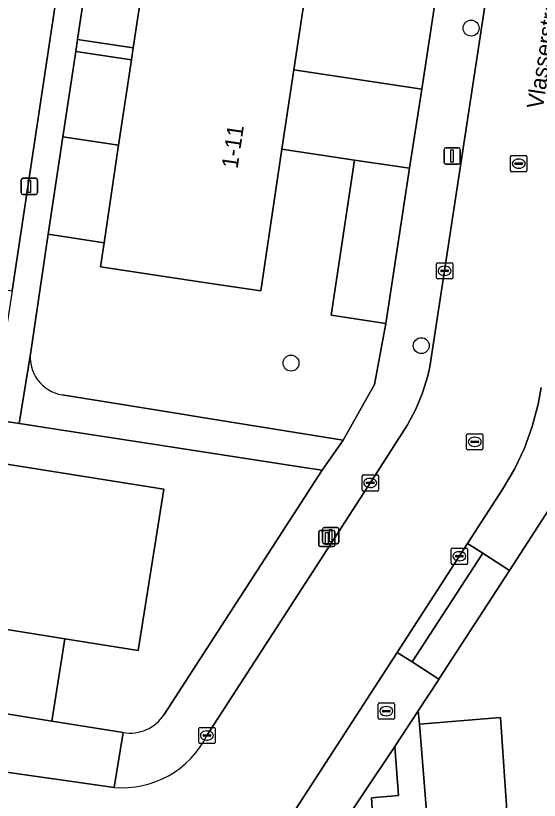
# Model space of a CAD drawing. Extents: x 161084 to 161928, y 385354 to 386522.
# Drawn here: x 161687.58 to 161719.79, y 385406.54 to 385454.78 of the extents above; entities that cross this region are included whole.
import ezdxf

# ---------------------------------------------------------------- set-up
doc = ezdxf.new("R2010")
doc.units = 0
for name, color, linetype in [('IMGEO_Boom', 7, 'Continuous'), ('IMGEO_Brandkraan', 7, 'Continuous'), ('IMGEO_Groenvoorziening', 7, 'Continuous'), ('IMGEO_Kolk', 7, 'Continuous'), ('IMGEO_Lichtmast', 7, 'Continuous'), ('IMGEO_Openbare_ruimte_label', 7, 'Continuous'), ('IMGEO_Pand', 7, 'Continuous'), ('IMGEO_Pand_nummerreeks', 7, 'Continuous'), ('IMGEO_Parkeervlak_open', 7, 'Continuous'), ('IMGEO_Rijbaan_lokaal_open', 7, 'Continuous'), ('IMGEO_Rioolput', 7, 'Continuous'), ('IMGEO_Voetpad_open', 7, 'Continuous')]:
    doc.layers.add(name, color=color, linetype=linetype)

msp = doc.modelspace()

# ---------------------------------------------------------------- linework, layer by layer
at = {"layer": 'IMGEO_Boom'}
for centre in [(161715.594, 385454.012), (161712.528, 385434.49), (161704.516, 385433.417)]:
    msp.add_circle(centre, 0.489, dxfattribs=at)
at = {"layer": 'IMGEO_Brandkraan'}
for p, q in [((161709.877, 385411.593), (161709.877, 385412.445)), ((161709.952, 385412.519), (161710.804, 385412.519)), ((161710.878, 385412.445), (161710.878, 385411.593)), ((161710.136, 385412.013), (161710.136, 385412.025)), ((161710.574, 385411.976), (161710.176, 385411.976)), ((161710.179, 385412.062), (161710.577, 385412.062)), ((161710.365, 385412.299), (161710.39, 385412.299)), ((161710.62, 385412.025), (161710.62, 385412.013)), ((161710.804, 385411.519), (161709.952, 385411.519)), ((161710.388, 385411.739), (161710.363, 385411.739))]:
    msp.add_line(p, q, dxfattribs=at)
for points in [[(161709.877, 385411.593), (161709.877, 385412.445)], [(161709.952, 385412.519), (161710.804, 385412.519)], [(161710.878, 385412.445), (161710.878, 385411.593)], [(161710.804, 385411.519), (161709.952, 385411.519)]]:
    msp.add_lwpolyline(points, dxfattribs=at)
for centre, radius, start, end in [((161709.954, 385412.443), 0.0765, 91.552, 178.448), ((161709.954, 385412.443), 0.0765, 91.552, 178.448), ((161710.802, 385412.443), 0.0765, 1.552, 88.448), ((161710.802, 385412.443), 0.0765, 1.552, 88.448), ((161710.176, 385412.022), 0.0403, 85.8775, 175.7526), ((161710.173, 385412.012), 0.0366, 178.938, 274.7102), ((161710.577, 385412.019), 0.043, 264.8664, 352.4533), ((161710.581, 385412.024), 0.0386, 1.7309, 96.639), ((161709.954, 385411.595), 0.0765, 181.552, 268.448), ((161709.954, 385411.595), 0.0765, 181.552, 268.448), ((161710.802, 385411.595), 0.0765, 271.552, 358.448), ((161710.802, 385411.595), 0.0765, 271.552, 358.448)]:
    msp.add_arc(centre, radius, start, end, dxfattribs=at)
for centre, major_axis, ratio, start_param, end_param in [((161710.364, 385412.019), (-0.387, 0.002), 0.722429, 4.712389, 7.853982), ((161710.389, 385412.019), (-0.39, 0.002), 0.717154, 1.570796, 4.712389)]:
    msp.add_ellipse(centre, major_axis=major_axis, ratio=ratio, start_param=start_param, end_param=end_param, dxfattribs=at)
at = {"layer": 'IMGEO_Groenvoorziening'}
for points in [[(161687.355, 385437.87), (161694.277, 385483.736), (161687.851, 385484.707), (161690.149, 385500), (161691.027, 385505.856), (161697.457, 385504.857), (161700.47, 385525.043), (161684.952, 385527.492), (161683.871, 385520.546), (161668.88, 385522.726), (161665.355, 385500), (161656.719, 385442.697)], [(161691.376, 385453.312), (161694.805, 385452.798), (161695.454, 385457.13), (161696.226, 385462.28), (161692.797, 385462.794)], [(161713.836, 385458.629), (161705.941, 385459.812), (161705.317, 385455.652), (161704.686, 385451.442), (161712.558, 385450.262)], [(161690.48, 385447.333), (161693.909, 385446.819), (161694.695, 385452.067), (161691.266, 385452.58)], [(161689.58, 385441.334), (161693.009, 385440.82), (161693.909, 385446.819), (161690.48, 385447.333)], [(161711.814, 385445.393), (161708.415, 385445.902), (161706.985, 385436.363), (161710.357, 385435.857)], [(161709.898, 385403.712), (161709.732, 385404.805), (161709.593, 385404.787), (161709.461, 385406.683), (161711.129, 385406.825), (161710.899, 385409.84), (161707.126, 385404.205), (161707.618, 385403.859), (161708.111, 385403.512)]]:
    msp.add_lwpolyline(points, close=True, dxfattribs=at)
for points in [[(161706.985, 385436.363), (161708.415, 385445.902), (161703.956, 385446.57), (161702.649, 385437.851), (161700.144, 385438.226), (161699.027, 385438.394), (161692.786, 385439.329), (161693.009, 385440.82), (161689.58, 385441.334), (161688.497, 385434.107)], [(161690.433, 385431.463), (161697.81, 385430.275), (161698.925, 385430.095), (161707.714, 385428.679), (161709.654, 385432.105), (161710.357, 385435.857), (161706.985, 385436.363)], [(161706.433, 385426.827), (161705.715, 385426.938), (161698.294, 385428.083), (161697.099, 385428.267), (161689.366, 385429.461), (161688.35, 385429.618), (161687.795, 385429.703), (161679.607, 385430.967), (161670.074, 385432.438), (161668.914, 385432.617), (161655.732, 385434.651), (161653.669, 385434.969), (161652.029, 385435.264)], [(161662.949, 385415.678), (161663.754, 385420.742), (161659.187, 385421.469), (161659.876, 385425.794), (161660.033, 385426.782), (161660.765, 385431.379), (161668.52, 385430.144), (161669.679, 385429.959), (161678.593, 385428.539), (161687.94, 385427.051), (161688.957, 385426.889), (161696.683, 385425.658), (161695.843, 385420.388), (161695.104, 385415.749), (161690.598, 385416.467), (161689.792, 385411.399), (161694.189, 385410.698)], [(161696.714, 385411.815), (161706.433, 385426.827)]]:
    msp.add_lwpolyline(points, dxfattribs=at)
for centre, radius, start, end in [((161690.802, 385433.764), 2.33, 171.5383, 260.8867), ((161694.593, 385413.198), 2.532, 260.8244, 326.9025)]:
    msp.add_arc(centre, radius, start, end, dxfattribs=at)
at = {"layer": 'IMGEO_Kolk'}
for p, q in [((161713.465, 385438.665), (161713.465, 385439.517)), ((161713.54, 385439.591), (161714.392, 385439.591)), ((161714.466, 385439.517), (161714.466, 385438.665)), ((161713.724, 385439.085), (161713.724, 385439.097)), ((161714.162, 385439.048), (161713.764, 385439.048)), ((161713.767, 385439.134), (161714.165, 385439.134)), ((161713.953, 385439.371), (161713.978, 385439.371)), ((161714.208, 385439.097), (161714.208, 385439.085)), ((161714.392, 385438.591), (161713.54, 385438.591)), ((161713.976, 385438.811), (161713.951, 385438.811)), ((161708.888, 385425.622), (161708.888, 385426.474)), ((161708.963, 385426.548), (161709.815, 385426.548)), ((161709.889, 385426.474), (161709.889, 385425.622)), ((161709.147, 385426.042), (161709.147, 385426.054)), ((161709.585, 385426.005), (161709.187, 385426.005)), ((161709.19, 385426.091), (161709.588, 385426.091)), ((161709.376, 385426.328), (161709.401, 385426.328)), ((161709.631, 385426.054), (161709.631, 385426.042)), ((161709.815, 385425.548), (161708.963, 385425.548)), ((161709.399, 385425.768), (161709.374, 385425.768)), ((161714.37, 385421.117), (161714.37, 385421.969)), ((161714.445, 385422.043), (161715.297, 385422.043)), ((161714.672, 385421.586), (161715.07, 385421.586)), ((161714.858, 385421.823), (161714.883, 385421.823)), ((161715.371, 385421.969), (161715.371, 385421.117)), ((161714.629, 385421.537), (161714.629, 385421.549)), ((161715.067, 385421.5), (161714.669, 385421.5)), ((161714.881, 385421.263), (161714.856, 385421.263)), ((161715.113, 385421.549), (161715.113, 385421.537)), ((161715.297, 385421.043), (161714.445, 385421.043)), ((161698.916, 385411.02), (161699.768, 385411.02)), ((161698.841, 385410.094), (161698.841, 385410.946)), ((161699.1, 385410.514), (161699.1, 385410.526)), ((161699.538, 385410.477), (161699.14, 385410.477)), ((161699.143, 385410.563), (161699.541, 385410.563)), ((161699.329, 385410.8), (161699.354, 385410.8)), ((161699.584, 385410.526), (161699.584, 385410.514)), ((161699.842, 385410.946), (161699.842, 385410.094)), ((161699.768, 385410.02), (161698.916, 385410.02)), ((161699.352, 385410.24), (161699.327, 385410.24))]:
    msp.add_line(p, q, dxfattribs=at)
for points in [[(161713.465, 385438.665), (161713.465, 385439.517)], [(161713.54, 385439.591), (161714.392, 385439.591)], [(161714.466, 385439.517), (161714.466, 385438.665)], [(161714.392, 385438.591), (161713.54, 385438.591)], [(161708.888, 385425.622), (161708.888, 385426.474)], [(161708.963, 385426.548), (161709.815, 385426.548)], [(161709.889, 385426.474), (161709.889, 385425.622)], [(161709.815, 385425.548), (161708.963, 385425.548)], [(161714.37, 385421.117), (161714.37, 385421.969)], [(161714.445, 385422.043), (161715.297, 385422.043)], [(161715.371, 385421.969), (161715.371, 385421.117)], [(161715.297, 385421.043), (161714.445, 385421.043)], [(161698.916, 385411.02), (161699.768, 385411.02)], [(161698.841, 385410.094), (161698.841, 385410.946)], [(161699.842, 385410.946), (161699.842, 385410.094)], [(161699.768, 385410.02), (161698.916, 385410.02)]]:
    msp.add_lwpolyline(points, dxfattribs=at)
for centre, radius, start, end in [((161713.542, 385439.515), 0.0765, 91.552, 178.448), ((161713.542, 385439.515), 0.0765, 91.552, 178.448), ((161714.39, 385439.515), 0.0765, 1.552, 88.448), ((161714.39, 385439.515), 0.0765, 1.552, 88.448), ((161713.764, 385439.094), 0.0403, 85.8775, 175.7526), ((161713.761, 385439.084), 0.0366, 178.938, 274.7102), ((161714.165, 385439.091), 0.043, 264.8664, 352.4533), ((161714.169, 385439.096), 0.0386, 1.7309, 96.639), ((161713.542, 385438.667), 0.0765, 181.552, 268.448), ((161713.542, 385438.667), 0.0765, 181.552, 268.448), ((161714.39, 385438.667), 0.0765, 271.552, 358.448), ((161714.39, 385438.667), 0.0765, 271.552, 358.448), ((161708.965, 385426.472), 0.0765, 91.552, 178.448), ((161708.965, 385426.472), 0.0765, 91.552, 178.448), ((161709.813, 385426.472), 0.0765, 1.552, 88.448), ((161709.813, 385426.472), 0.0765, 1.552, 88.448), ((161709.187, 385426.051), 0.0403, 85.8775, 175.7526), ((161709.184, 385426.041), 0.0366, 178.938, 274.7102), ((161709.588, 385426.048), 0.043, 264.8664, 352.4533), ((161709.592, 385426.053), 0.0386, 1.7309, 96.639), ((161708.965, 385425.624), 0.0765, 181.552, 268.448), ((161708.965, 385425.624), 0.0765, 181.552, 268.448), ((161709.813, 385425.624), 0.0765, 271.552, 358.448), ((161709.813, 385425.624), 0.0765, 271.552, 358.448), ((161714.447, 385421.967), 0.0765, 91.552, 178.448), ((161714.447, 385421.967), 0.0765, 91.552, 178.448), ((161714.669, 385421.546), 0.0403, 85.8775, 175.7526), ((161715.074, 385421.548), 0.0386, 1.7309, 96.639), ((161715.295, 385421.967), 0.0765, 1.552, 88.448), ((161715.295, 385421.967), 0.0765, 1.552, 88.448), ((161714.447, 385421.119), 0.0765, 181.552, 268.448), ((161714.447, 385421.119), 0.0765, 181.552, 268.448), ((161714.666, 385421.536), 0.0366, 178.938, 274.7102), ((161715.07, 385421.543), 0.043, 264.8664, 352.4533), ((161715.295, 385421.119), 0.0765, 271.552, 358.448), ((161715.295, 385421.119), 0.0765, 271.552, 358.448), ((161698.918, 385410.944), 0.0765, 91.552, 178.448), ((161698.918, 385410.944), 0.0765, 91.552, 178.448), ((161699.766, 385410.944), 0.0765, 1.552, 88.448), ((161699.766, 385410.944), 0.0765, 1.552, 88.448), ((161699.14, 385410.523), 0.0403, 85.8775, 175.7526), ((161699.137, 385410.513), 0.0366, 178.938, 274.7102), ((161699.541, 385410.52), 0.043, 264.8664, 352.4533), ((161699.545, 385410.525), 0.0386, 1.7309, 96.639), ((161698.918, 385410.096), 0.0765, 181.552, 268.448), ((161698.918, 385410.096), 0.0765, 181.552, 268.448), ((161699.766, 385410.096), 0.0765, 271.552, 358.448), ((161699.766, 385410.096), 0.0765, 271.552, 358.448)]:
    msp.add_arc(centre, radius, start, end, dxfattribs=at)
for centre, major_axis, ratio, start_param, end_param in [((161713.952, 385439.091), (-0.387, 0.002), 0.722429, 4.712389, 7.853982), ((161713.977, 385439.091), (-0.39, 0.002), 0.717154, 1.570796, 4.712389), ((161709.375, 385426.048), (-0.387, 0.002), 0.722429, 4.712389, 7.853982), ((161709.4, 385426.048), (-0.39, 0.002), 0.717154, 1.570796, 4.712389), ((161714.857, 385421.543), (-0.387, 0.002), 0.722429, 4.712389, 7.853982), ((161714.882, 385421.543), (-0.39, 0.002), 0.717154, 1.570796, 4.712389), ((161699.328, 385410.52), (-0.387, 0.002), 0.722429, 4.712389, 7.853982), ((161699.353, 385410.52), (-0.39, 0.002), 0.717154, 1.570796, 4.712389)]:
    msp.add_ellipse(centre, major_axis=major_axis, ratio=ratio, start_param=start_param, end_param=end_param, dxfattribs=at)
at = {"layer": 'IMGEO_Lichtmast'}
for p, q in [((161714.03, 385446.655), (161714.82, 385446.655)), ((161714.82, 385446.655), (161714.03, 385446.655)), ((161713.93, 385445.755), (161713.93, 385446.555)), ((161713.93, 385446.555), (161713.93, 385445.755)), ((161714.92, 385446.555), (161714.92, 385445.755)), ((161714.92, 385445.755), (161714.92, 385446.555)), ((161714.82, 385445.655), (161714.03, 385445.655)), ((161714.03, 385445.655), (161714.82, 385445.655)), ((161688.02, 385444.783), (161688.81, 385444.783)), ((161688.81, 385444.783), (161688.02, 385444.783)), ((161687.92, 385443.883), (161687.92, 385444.683)), ((161687.92, 385444.683), (161687.92, 385443.883)), ((161688.91, 385444.683), (161688.91, 385443.883)), ((161688.91, 385443.883), (161688.91, 385444.683)), ((161688.81, 385443.783), (161688.02, 385443.783)), ((161688.02, 385443.783), (161688.81, 385443.783)), ((161706.224, 385422.233), (161706.224, 385423.033)), ((161706.224, 385423.033), (161706.224, 385422.233)), ((161706.324, 385423.133), (161707.114, 385423.133)), ((161707.114, 385423.133), (161706.324, 385423.133)), ((161706.46, 385422.409), (161706.46, 385423.209)), ((161706.46, 385423.209), (161706.46, 385422.409)), ((161706.56, 385423.309), (161707.35, 385423.309)), ((161707.35, 385423.309), (161706.56, 385423.309)), ((161707.214, 385423.033), (161707.214, 385422.233)), ((161707.214, 385422.233), (161707.214, 385423.033)), ((161707.45, 385423.209), (161707.45, 385422.409)), ((161707.45, 385422.409), (161707.45, 385423.209)), ((161707.114, 385422.133), (161706.324, 385422.133)), ((161706.324, 385422.133), (161707.114, 385422.133)), ((161707.35, 385422.309), (161706.56, 385422.309)), ((161706.56, 385422.309), (161707.35, 385422.309))]:
    msp.add_line(p, q, dxfattribs=at)
for points in [[(161714.35, 385446.53), (161714.5, 385446.53), (161714.5, 385445.78), (161714.35, 385445.78), (161714.35, 385446.53)], [(161688.34, 385444.658), (161688.49, 385444.658), (161688.49, 385443.908), (161688.34, 385443.908), (161688.34, 385444.658)], [(161706.88, 385423.184), (161707.03, 385423.184), (161707.03, 385422.434), (161706.88, 385422.434), (161706.88, 385423.184)], [(161706.644, 385423.008), (161706.794, 385423.008), (161706.794, 385422.258), (161706.644, 385422.258), (161706.644, 385423.008)]]:
    msp.add_lwpolyline(points, dxfattribs=at)
for centre, start, end in [((161714.03, 385446.555), 90, 180), ((161714.03, 385446.555), 90, 180), ((161714.82, 385446.555), 0, 90), ((161714.82, 385446.555), 360, 90), ((161714.03, 385445.755), 180, 270), ((161714.03, 385445.755), 180, 270), ((161714.82, 385445.755), 270, 0), ((161714.82, 385445.755), 270, 0), ((161688.02, 385444.683), 90, 180), ((161688.02, 385444.683), 90, 180), ((161688.81, 385444.683), 0, 90), ((161688.81, 385444.683), 360, 90), ((161688.02, 385443.883), 180, 270), ((161688.02, 385443.883), 180, 270), ((161688.81, 385443.883), 270, 0), ((161688.81, 385443.883), 270, 0), ((161706.324, 385423.033), 90, 180), ((161706.324, 385423.033), 90, 180), ((161706.56, 385423.209), 90, 180), ((161706.56, 385423.209), 90, 180), ((161707.114, 385423.033), 0, 90), ((161707.114, 385423.033), 360, 90), ((161707.35, 385423.209), 0, 90), ((161707.35, 385423.209), 360, 90), ((161706.324, 385422.233), 180, 270), ((161706.324, 385422.233), 180, 270), ((161706.56, 385422.409), 180, 270), ((161706.56, 385422.409), 180, 270), ((161707.114, 385422.233), 270, 0), ((161707.114, 385422.233), 270, 0), ((161707.35, 385422.409), 270, 0), ((161707.35, 385422.409), 270, 0)]:
    msp.add_arc(centre, 0.1, start, end, dxfattribs=at)
at = {"layer": 'IMGEO_Pand'}
for points in [[(161705.317, 385455.652), (161695.454, 385457.13), (161694.805, 385452.798), (161694.695, 385452.067), (161693.909, 385446.819), (161693.009, 385440.82), (161692.786, 385439.329), (161699.027, 385438.394), (161700.144, 385438.226), (161702.649, 385437.851), (161703.956, 385446.57), (161704.686, 385451.442)], [(161683.3, 385417.629), (161687.035, 385417.034), (161690.598, 385416.467), (161695.104, 385415.749), (161695.843, 385420.388), (161696.683, 385425.658), (161688.957, 385426.889), (161687.94, 385427.051), (161678.593, 385428.539), (161677.015, 385418.63)]]:
    msp.add_lwpolyline(points, close=True, dxfattribs=at)
at = {"layer": 'IMGEO_Parkeervlak_open'}
msp.add_lwpolyline([(161717.4, 385411.626), (161712.409, 385411.224), (161713.131, 385402.28), (161718.019, 385402.612)], close=True, dxfattribs=at)
at = {"layer": 'IMGEO_Rijbaan_lokaal_open'}
for points in [[(161723.237, 385500), (161713.061, 385433.189), (161712.927, 385432.624), (161712.605, 385431.585), (161712.19, 385430.579), (161711.688, 385429.614), (161709.663, 385426.482), (161699.341, 385410.516)], [(161704.565, 385405.627), (161711.043, 385415.632), (161715.381, 385422.332), (161717.547, 385425.678), (161718.264, 385426.902), (161718.869, 385428.185), (161719.356, 385429.517), (161719.723, 385430.887), (161719.914, 385431.913)], [(161720.617, 385424.785), (161717.947, 385420.67), (161713.609, 385413.983), (161713.603, 385413.974), (161712.344, 385412.033), (161712.409, 385411.224), (161717.4, 385411.626), (161718.019, 385402.612), (161724.677, 385403.063)], [(161693.625, 385407.334), (161671.022, 385410.55), (161662.632, 385411.873), (161658.399, 385412.541), (161654.604, 385413.143)]]:
    msp.add_lwpolyline(points, dxfattribs=at)
msp.add_arc((161694.128, 385413.155), 5.843, 265.0607, 333.1472, dxfattribs=at)
at = {"layer": 'IMGEO_Rioolput'}
for p, q in [((161718.098, 385446.18), (161718.95, 385446.18)), ((161718.023, 385445.254), (161718.023, 385446.106)), ((161718.282, 385445.674), (161718.282, 385445.686)), ((161718.325, 385445.723), (161718.723, 385445.723)), ((161718.511, 385445.96), (161718.536, 385445.96)), ((161718.766, 385445.686), (161718.766, 385445.674)), ((161719.024, 385446.106), (161719.024, 385445.254)), ((161718.72, 385445.637), (161718.322, 385445.637)), ((161718.534, 385445.4), (161718.509, 385445.4)), ((161718.95, 385445.18), (161718.098, 385445.18)), ((161715.319, 385428.15), (161715.319, 385429.002)), ((161715.394, 385429.076), (161716.246, 385429.076)), ((161715.807, 385428.856), (161715.832, 385428.856)), ((161716.32, 385429.002), (161716.32, 385428.15)), ((161715.578, 385428.57), (161715.578, 385428.582)), ((161716.016, 385428.533), (161715.618, 385428.533)), ((161715.621, 385428.619), (161716.019, 385428.619)), ((161716.062, 385428.582), (161716.062, 385428.57)), ((161716.246, 385428.076), (161715.394, 385428.076)), ((161715.83, 385428.296), (161715.805, 385428.296))]:
    msp.add_line(p, q, dxfattribs=at)
for points in [[(161718.098, 385446.18), (161718.95, 385446.18)], [(161718.023, 385445.254), (161718.023, 385446.106)], [(161719.024, 385446.106), (161719.024, 385445.254)], [(161718.95, 385445.18), (161718.098, 385445.18)], [(161715.319, 385428.15), (161715.319, 385429.002)], [(161715.394, 385429.076), (161716.246, 385429.076)], [(161716.32, 385429.002), (161716.32, 385428.15)], [(161716.246, 385428.076), (161715.394, 385428.076)]]:
    msp.add_lwpolyline(points, dxfattribs=at)
for centre, radius, start, end in [((161718.1, 385446.104), 0.0765, 91.552, 178.448), ((161718.1, 385446.104), 0.0765, 91.552, 178.448), ((161718.948, 385446.104), 0.0765, 1.552, 88.448), ((161718.948, 385446.104), 0.0765, 1.552, 88.448), ((161718.322, 385445.683), 0.0403, 85.8775, 175.7526), ((161718.727, 385445.685), 0.0386, 1.7309, 96.639), ((161718.1, 385445.256), 0.0765, 181.552, 268.448), ((161718.1, 385445.256), 0.0765, 181.552, 268.448), ((161718.319, 385445.673), 0.0366, 178.938, 274.7102), ((161718.723, 385445.68), 0.043, 264.8664, 352.4533), ((161718.948, 385445.256), 0.0765, 271.552, 358.448), ((161718.948, 385445.256), 0.0765, 271.552, 358.448), ((161715.396, 385429), 0.0765, 91.552, 178.448), ((161715.396, 385429), 0.0765, 91.552, 178.448), ((161716.244, 385429), 0.0765, 1.552, 88.448), ((161716.244, 385429), 0.0765, 1.552, 88.448), ((161715.618, 385428.579), 0.0403, 85.8775, 175.7526), ((161715.615, 385428.569), 0.0366, 178.938, 274.7102), ((161716.019, 385428.576), 0.043, 264.8664, 352.4533), ((161716.023, 385428.581), 0.0386, 1.7309, 96.639), ((161715.396, 385428.152), 0.0765, 181.552, 268.448), ((161715.396, 385428.152), 0.0765, 181.552, 268.448), ((161716.244, 385428.152), 0.0765, 271.552, 358.448), ((161716.244, 385428.152), 0.0765, 271.552, 358.448)]:
    msp.add_arc(centre, radius, start, end, dxfattribs=at)
for centre, major_axis, ratio, start_param, end_param in [((161718.51, 385445.68), (-0.387, 0.002), 0.722429, 4.712389, 7.853982), ((161718.535, 385445.68), (-0.39, 0.002), 0.717154, 1.570796, 4.712389), ((161715.806, 385428.576), (-0.387, 0.002), 0.722429, 4.712389, 7.853982), ((161715.831, 385428.576), (-0.39, 0.002), 0.717154, 1.570796, 4.712389)]:
    msp.add_ellipse(centre, major_axis=major_axis, ratio=ratio, start_param=start_param, end_param=end_param, dxfattribs=at)
at = {"layer": 'IMGEO_Voetpad_open'}
for points in [[(161699.341, 385410.516), (161709.663, 385426.482), (161711.688, 385429.614), (161712.19, 385430.579), (161712.605, 385431.585), (161712.927, 385432.624), (161713.061, 385433.189), (161723.237, 385500), (161727.669, 385529.274), (161727.823, 385530.11), (161731.045, 385551.389), (161732.828, 385563.446)], [(161656.268, 385438.891), (161655.732, 385434.651), (161668.914, 385432.617), (161670.074, 385432.438), (161679.607, 385430.967), (161687.795, 385429.703), (161688.497, 385434.107), (161689.58, 385441.334), (161690.48, 385447.333), (161691.266, 385452.58), (161691.376, 385453.312), (161692.797, 385462.794), (161692.94, 385463.744), (161696.643, 385488.449), (161696.796, 385489.473), (161698.167, 385498.626), (161698.304, 385499.531), (161698.375, 385500), (161701.928, 385523.472), (161702.137, 385524.559), (161707.374, 385558.705)], [(161707.374, 385558.705), (161705.534, 385558.969), (161704.956, 385555.095), (161702.756, 385540.358), (161702.189, 385536.561), (161700.47, 385525.043), (161697.457, 385504.857), (161696.732, 385500), (161694.277, 385483.736), (161687.355, 385437.87), (161686.853, 385434.542)], [(161720.039, 385499.232), (161719.339, 385494.65), (161718.003, 385485.908), (161717.296, 385481.276), (161714.579, 385463.494), (161713.836, 385458.629), (161712.558, 385450.262), (161711.814, 385445.393), (161710.357, 385435.857), (161709.654, 385432.105), (161707.714, 385428.679), (161706.433, 385426.827), (161696.714, 385411.815)], [(161688.497, 385434.107), (161687.795, 385429.703), (161688.35, 385429.618), (161689.366, 385429.461), (161697.099, 385428.267), (161698.294, 385428.083), (161705.715, 385426.938), (161706.433, 385426.827), (161707.714, 385428.679), (161698.925, 385430.095)], [(161719.914, 385431.913), (161719.723, 385430.887), (161719.356, 385429.517), (161718.869, 385428.185), (161718.264, 385426.902), (161717.547, 385425.678), (161715.381, 385422.332), (161716.311, 385421.731), (161717.947, 385420.67), (161720.617, 385424.785)], [(161698.925, 385430.095), (161697.81, 385430.275), (161690.433, 385431.463)], [(161662.521, 385415.355), (161655.13, 385416.518), (161654.604, 385413.143), (161658.399, 385412.541), (161662.632, 385411.873), (161671.022, 385410.55), (161693.625, 385407.334), (161694.189, 385410.698), (161689.792, 385411.399), (161686.229, 385411.967), (161682.494, 385412.562)], [(161707.126, 385404.205), (161710.899, 385409.84), (161712.344, 385412.033), (161713.603, 385413.974), (161713.609, 385413.983), (161711.973, 385415.044), (161711.043, 385415.632), (161704.565, 385405.627)], [(161694.189, 385410.698), (161693.625, 385407.334)]]:
    msp.add_lwpolyline(points, dxfattribs=at)
for points in [[(161691.266, 385452.58), (161694.695, 385452.067), (161694.805, 385452.798), (161691.376, 385453.312)], [(161712.558, 385450.262), (161704.686, 385451.442), (161703.956, 385446.57), (161708.415, 385445.902), (161711.814, 385445.393)], [(161715.381, 385422.332), (161711.043, 385415.632), (161711.973, 385415.044), (161716.311, 385421.731)], [(161717.947, 385420.67), (161716.311, 385421.731), (161711.973, 385415.044), (161713.609, 385413.983)], [(161689.792, 385411.399), (161690.598, 385416.467), (161687.035, 385417.034), (161686.229, 385411.967)], [(161712.409, 385411.224), (161712.344, 385412.033), (161710.899, 385409.84), (161711.129, 385406.825), (161709.461, 385406.683), (161709.593, 385404.787), (161709.732, 385404.805), (161709.898, 385403.712), (161708.111, 385403.512), (161704.314, 385399.024), (161706.035, 385399.138), (161705.989, 385399.83), (161707.567, 385401.634), (161709.571, 385401.767), (161713.131, 385402.28)]]:
    msp.add_lwpolyline(points, close=True, dxfattribs=at)
for centre, radius, start, end in [((161690.802, 385433.764), 2.33, 171.5383, 260.8867), ((161694.593, 385413.198), 2.532, 260.8244, 326.9025), ((161694.128, 385413.155), 5.843, 265.0607, 333.1472)]:
    msp.add_arc(centre, radius, start, end, dxfattribs=at)

# ---------------------------------------------------------------- texts
at = {"layer": 'IMGEO_Openbare_ruimte_label'}
msp.add_text('Vlasserstraat', height=1, rotation=81.3191, dxfattribs=at).set_placement((161720.004, 385448.998))
at = {"layer": 'IMGEO_Pand_nummerreeks'}
msp.add_text('1-11', height=1, rotation=81.4752, dxfattribs=at).set_placement((161701.223, 385445.335))

doc.saveas('drawing.dxf')
